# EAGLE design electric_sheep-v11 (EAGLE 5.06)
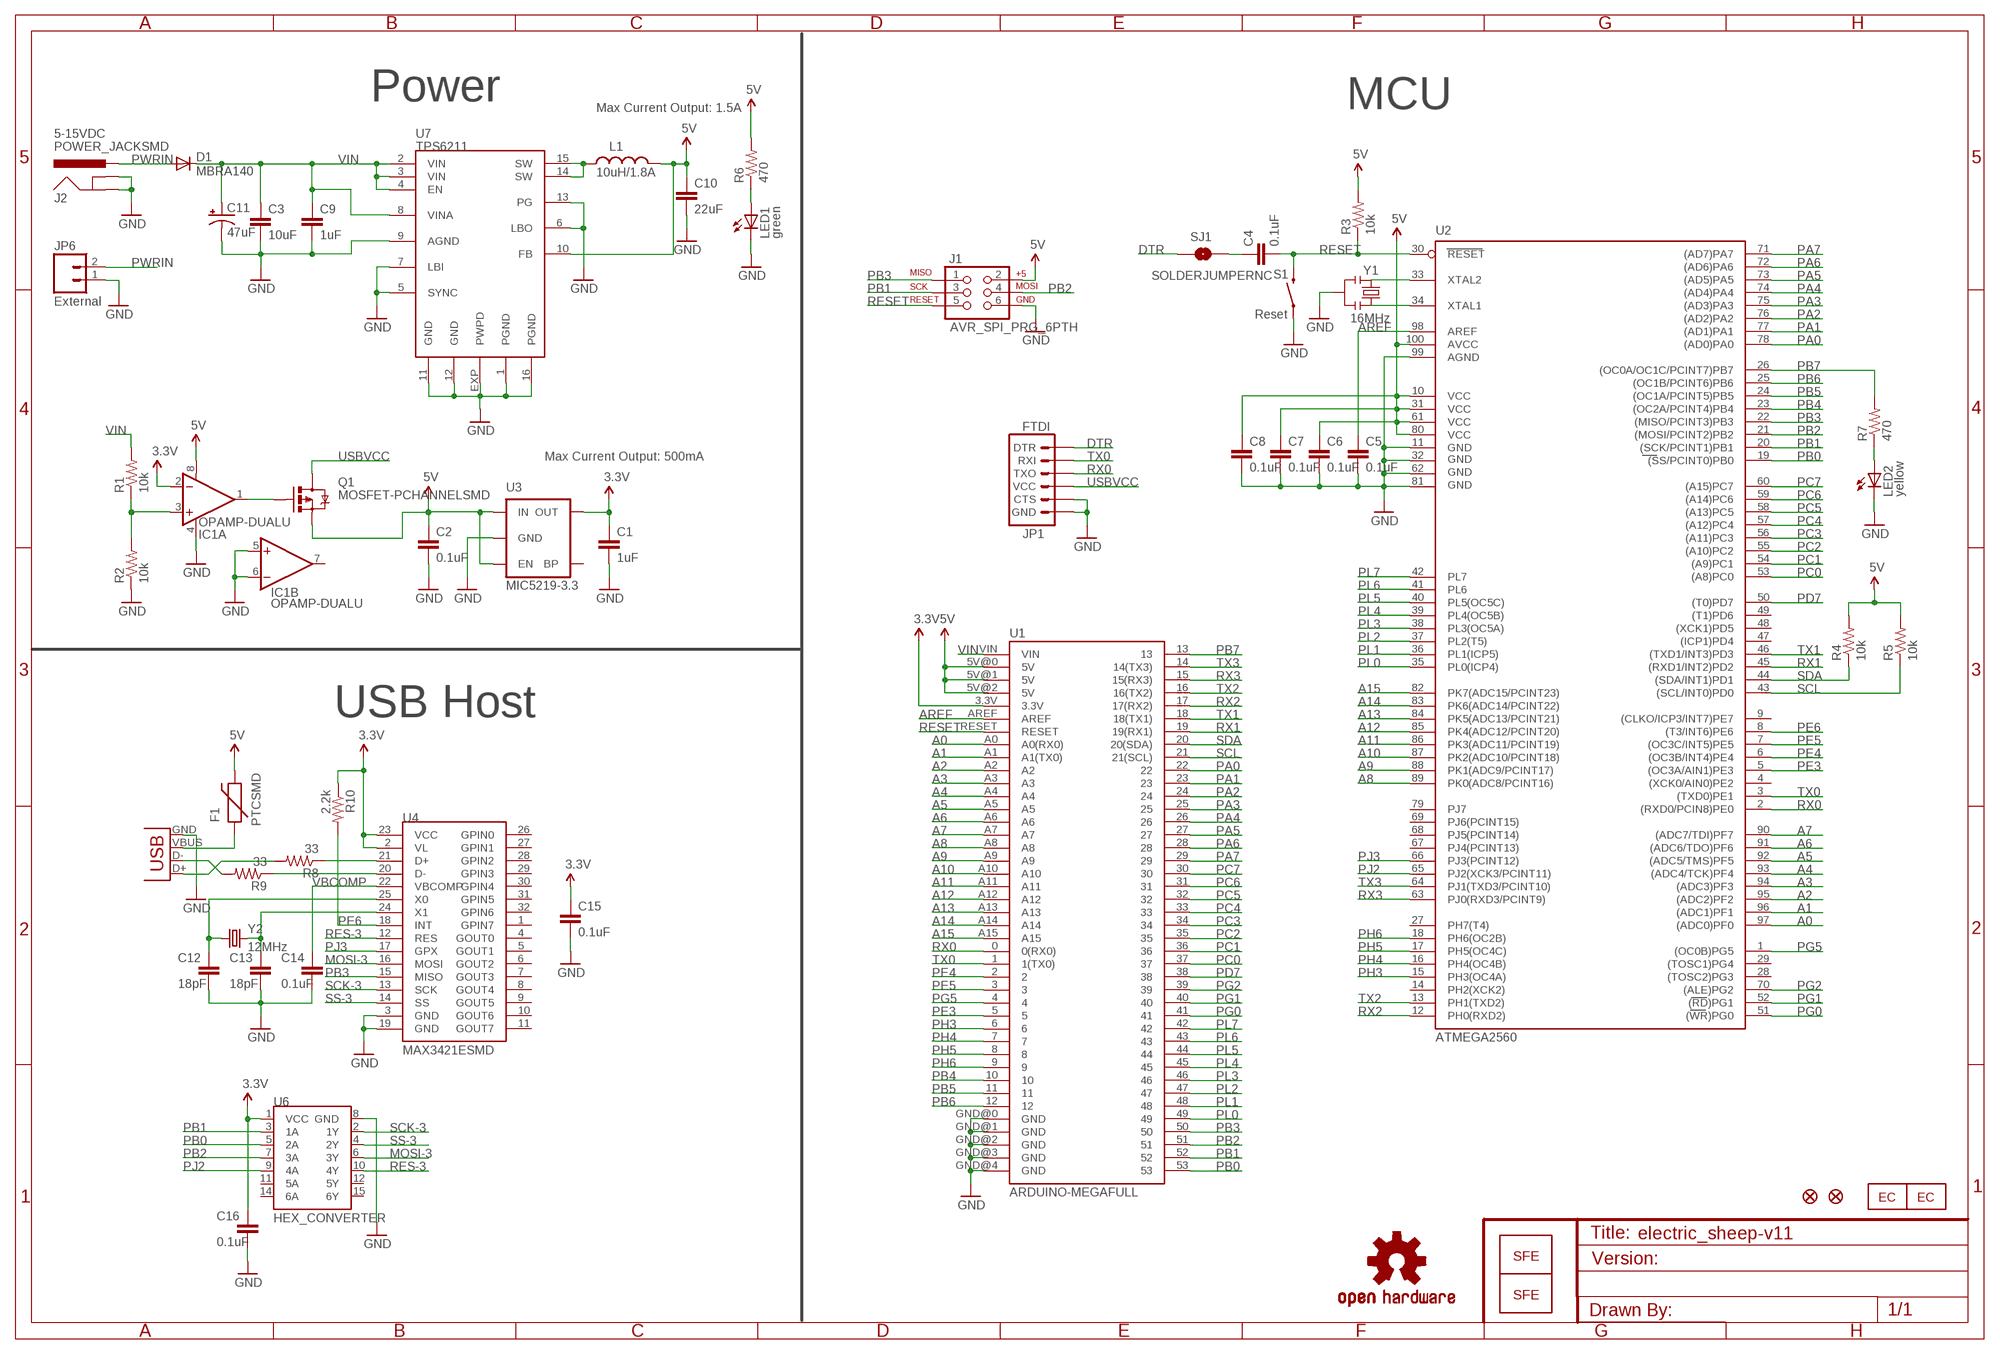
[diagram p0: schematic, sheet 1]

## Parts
C1  1uF  CAP0402-CAP  [0402-CAP]
C2  0.1uF  CAP0402-CAP  [0402-CAP]
C3  10uF  CAP1210  [1210]
C4  0.1uF  CAP0402-CAP  [0402-CAP]
C5  0.1uF  CAP0402-CAP  [0402-CAP]
C6  0.1uF  CAP0402-CAP  [0402-CAP]
C7  0.1uF  CAP0402-CAP  [0402-CAP]
C8  0.1uF  CAP0402-CAP  [0402-CAP]
C9  1uF  CAP0402-CAP  [0402-CAP]
C10  22uF  CAP1210  [1210]
C11  47uF  CAP_POLD  [PANASONIC_D]
C12  18pF  CAP0402-CAP  [0402-CAP]
C13  18pF  CAP0402-CAP  [0402-CAP]
C14  0.1uF  CAP0402-CAP  [0402-CAP]
C15  0.1uF  CAP0402-CAP  [0402-CAP]
C16  0.1uF  CAP0402-CAP  [0402-CAP]
D1  MBRA140  DIODESMA  [SMA-DIODE]
F1  PTCSMD  [PTC-1206]
IC1  OPAMP-DUALU  [SO08]
J1  AVR_SPI_PRG_6PTH  [2X3]
J2  POWER_JACKSMD  [POWER_JACK_SMD]
JP1  FTDI  ARDUINO_SERIAL_PROGRAMSMD  [1X06-SMD]
JP2  LOGO-SFENEW  [SFE-NEW-WEBLOGO]
JP3  LOGO-SFENEW  [SFE-NEW-WEBLOGO]
JP4  FIDUCIAL1X2.5  [FIDUCIAL-1X2.5]
JP5  FIDUCIAL1X2.5  [FIDUCIAL-1X2.5]
JP6  External  M02PTH  [1X02]
L1  10uH/1.8A  INDUCTORSRU5028  [SRU5028]
LED1  green  LED0603  [LED-0603]
LED2  yellow  LED0603  [LED-0603]
Q1  MOSFET-PCHANNELSMD  [SOT23-3]
R1  10k  RESISTOR0402-RES  [0402-RES]
R2  10k  RESISTOR0402-RES  [0402-RES]
R3  10k  RESISTOR0402-RES  [0402-RES]
R4  10k  RESISTOR0402-RES  [0402-RES]
R5  10k  RESISTOR0402-RES  [0402-RES]
R6  470  RESISTOR0402-RES  [0402-RES]
R7  470  RESISTOR0402-RES  [0402-RES]
R8  33  RESISTOR0402-RES  [0402-RES]
R9  33  RESISTOR0402-RES  [0402-RES]
R10  2.2k  RESISTOR0402-RES  [0402-RES]
S1  SWITCH-MOMENTARY-2SMD  [TACTILE_SWITCH_SMD]
SJ1  SOLDERJUMPERNC  [SJ_2S]
U1  ARDUINO-MEGAFULL  [ARDUINO_MEGA]
U2  ATMEGA2560AU  [TQFP100]
U3  V_REG_LDOSMD  [SOT23-5]
U4  MAX3421ESMD  [TQFP32-5MM]
U6  HEX_CONVERTER  [SO016]
U7  TPS6211  [QFN16-4X4]
U$1  OSHW-LOGOL  [OSHW-LOGO-L]
U$14  ANDROID-ELECTRIC_SHEEP_LOGO_  [ANDROID-ELECTRIC_SHEEP_LOGO]
U$15  ANDROID-ELECTRIC_SHEEP_LOGO_  [ANDROID-ELECTRIC_SHEEP_LOGO]
X1  USB-A-SMD  [USB-A-S-NOSILK-FEMALE]
Y1  RESONATORSMD  [RESONATOR-SMD]
Y2  12MHz  CRYSTAL5X3  [CRYSTAL-SMD-5X3]

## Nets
3.3V: C1.1 C15.1 C16.1 IC1.2(A:-IN) R10.1 U1.3.3V U3.5(OUT) U4.2(VL) U4.23(VCC) U6.1(VCC)
5V: C2.1 C6.1 C7.1 C8.1 C10.1 F1.2 IC1.8(A:V+) J1.2 L1.2 Q1.2(S) R3.2 R4.2 R5.2 R6.2 U1.5V@0(5V) U1.5V@1(5V) U1.5V@2(5V) U2.10(VCC) U2.31(VCC1) U2.61(VCC2) U2.80(VCC3) U2.100(AVCC) U3.1(IN) U3.3(EN) U7.10(FB)
A0: U1.A0(A0(RX0)) U2.97((ADC0)PF0)
A1: U1.A1(A1(TX0)) U2.96((ADC1)PF1)
A2: U1.A2 U2.95((ADC2)PF2)
A3: U1.A3 U2.94((ADC3)PF3)
A4: U1.A4 U2.93((ADC4/TCK)PF4)
A5: U1.A5 U2.92((ADC5/TMS)PF5)
A6: U1.A6 U2.91((ADC6/TDO)PF6)
A7: U1.A7 U2.90((ADC7/TDI)PF7)
A8: U1.A8 U2.89(PK0(ADC8/PCINT16))
A9: U1.A9 U2.88(PK1(ADC9/PCINT17))
A10: U1.A10 U2.87(PK2(ADC10/PCINT18))
A11: U1.A11 U2.86(PK3(ADC11/PCINT19))
A12: U1.A12 U2.85(PK4(ADC12/PCINT20))
A13: U1.A13 U2.84(PK5(ADC13/PCINT21))
A14: U1.A14 U2.83(PK6(ADC14/PCINT22))
A15: U1.A15 U2.82(PK7(ADC15/PCINT23))
AREF: C5.1 U1.AREF U2.98(AREF)
DTR: JP1.1(DTR) SJ1.1
GND: C1.2 C2.2 C3.2 C5.2 C6.2 C7.2 C8.2 C9.2 C10.2 C11.- C12.2 C13.2 C14.2 C15.2 C16.2 IC1.4(A:V-) IC1.5(B:+IN) IC1.6(B:-IN) J1.6 J2.GND(GNDBREAK) J2.P$4(GND) JP1.5(CTS) JP1.6(GND) JP6.1 LED1.C LED2.C R2.1 S1.1 U1.GND@0(GND) U1.GND@1(GND) U1.GND@2(GND) U1.GND@3(GND) U1.GND@4(GND) U2.11(GND) U2.32(GND1) U2.62(GND2) U2.81(GND3) U2.99(AGND) U3.2(GND) U4.3(GND) U4.19(GND) U6.8(GND) U7.1(PGND) U7.5(SYNC) U7.6(LBO) U7.7(LBI) U7.9(AGND) U7.11(GND) U7.12(GND) U7.13(PG) U7.16(PGND) U7.EXP(PWPD) X1.GND Y1.2
MOSI-3: U4.16(MOSI) U6.6(3Y)
N$1: IC1.3(A:+IN) R1.1 R2.2
N$2: LED1.A R6.1
N$3: LED2.A R7.1
N$4: C4.1 SJ1.2
N$5: IC1.1(A:OUT) Q1.1(G)
N$11: L1.1 U7.14(SW) U7.15(SW)
N$13: R8.1 U4.21(D+)
N$14: R9.1 U4.20(D-)
N$15: R9.2 X1.D-
N$16: R8.2 X1.D+
N$18: F1.1 X1.VBUS
N$19: C12.1 U4.25(X0) Y2.1
N$20: C13.1 U4.24(X1) Y2.3
N$73: U2.33(XTAL2) Y1.1
N$74: U2.34(XTAL1) Y1.3
PA0: U1.22 U2.78((AD0)PA0)
PA1: U1.23 U2.77((AD1)PA1)
PA2: U1.24 U2.76((AD2)PA2)
PA3: U1.25 U2.75((AD3)PA3)
PA4: U1.26 U2.74((AD4)PA4)
PA5: U1.27 U2.73((AD5)PA5)
PA6: U1.28 U2.72((AD6)PA6)
PA7: U1.29 U2.71((AD7)PA7)
PB0: U1.53 U2.19((SS/PCINT0)PB0) U6.5(2A)
PB1: J1.3 U1.52 U2.20((SCK/PCINT1)PB1) U6.3(1A)
PB2: J1.4 U1.51 U2.21((MOSI/PCINT2)PB2) U6.7(3A)
PB3: J1.1 U1.50 U2.22((MISO/PCINT3)PB3) U4.15(MISO)
PB4: U1.10 U2.23((OC2A/PCINT4)PB4)
PB5: U1.11 U2.24((OC1A/PCINT5)PB5)
PB6: U1.12 U2.25((OC1B/PCINT6)PB6)
PB7: R7.2 U1.13 U2.26((OC0A/OC1C/PCINT7)PB7)
PC0: U1.37 U2.53((A8)PC0)
PC1: U1.36 U2.54((A9)PC1)
PC2: U1.35 U2.55((A10)PC2)
PC3: U1.34 U2.56((A11)PC3)
PC4: U1.33 U2.57((A12)PC4)
PC5: U1.32 U2.58((A13)PC5)
PC6: U1.31 U2.59((A14)PC6)
PC7: U1.30 U2.60((A15)PC7)
PD7: U1.38 U2.50((T0)PD7)
PE3: U1.5 U2.5((OC3A/AIN1)PE3)
PE4: U1.2 U2.6((OC3B/INT4)PE4)
PE5: U1.3 U2.7((OC3C/INT5)PE5)
PE6: R10.2 U2.8((T3/INT6)PE6) U4.18(INT)
PG0: U1.41 U2.51((WR)PG0)
PG1: U1.40 U2.52((RD)PG1)
PG2: U1.39 U2.70((ALE)PG2)
PG5: U1.4 U2.1((OC0B)PG5)
PH3: U1.6 U2.15(PH3(OC4A))
PH4: U1.7 U2.16(PH4(OC4B))
PH5: U1.8 U2.17(PH5(OC4C))
PH6: U1.9 U2.18(PH6(OC2B))
PJ2: U2.65(PJ2(XCK3/PCINT11)) U6.9(4A)
PJ3: U2.66(PJ3(PCINT12)) U4.17(GPX)
PL0: U1.49 U2.35(PL0(ICP4))
PL1: U1.48 U2.36(PL1(ICP5))
PL2: U1.47 U2.37(PL2(T5))
PL3: U1.46 U2.38(PL3(OC5A))
PL4: U1.45 U2.39(PL4(OC5B))
PL5: U1.44 U2.40(PL5(OC5C))
PL6: U1.43 U2.41(PL6)
PL7: U1.42 U2.42(PL7)
PWRIN: D1.A J2.VIN0(PWR) JP6.2
RES-3: U4.12(RES) U6.10(4Y)
RESET: C4.2 J1.5 R3.1 S1.3 U1.RESET U2.30(RESET)
RX0: JP1.3(TXO) U1.0(0(RX0)) U2.2((RXD0/PCIN8)PE0)
RX1: U1.19(19(RX1)) U2.45((RXD1/INT2)PD2)
RX2: U1.17(17(RX2)) U2.12(PH0(RXD2))
RX3: U1.15(15(RX3)) U2.63(PJ0(RXD3/PCINT9))
SCK-3: U4.13(SCK) U6.2(1Y)
SCL: R5.1 U1.21(21(SCL)) U2.43((SCL/INT0)PD0)
SDA: R4.1 U1.20(20(SDA)) U2.44((SDA/INT1)PD1)
SS-3: U4.14(SS) U6.4(2Y)
TX0: JP1.2(RXI) U1.1(1(TX0)) U2.3((TXD0)PE1)
TX1: U1.18(18(TX1)) U2.46((TXD1/INT3)PD3)
TX2: U1.16(16(TX2)) U2.13(PH1(TXD2))
TX3: U1.14(14(TX3)) U2.64(PJ1(TXD3/PCINT10))
USBVCC: JP1.4(VCC) Q1.3(D)
VBCOMP: C14.1 U4.22(VBCOMP)
VIN: C3.1 C9.1 C11.+ D1.C R1.2 U1.VIN U7.2(VIN) U7.3(VIN) U7.4(EN) U7.8(VINA)
Unconnected: IC1.7(B:OUT) U2.4((XCK0/AIN0)PE2) U2.9((CLKO/ICP3/INT7)PE7) U2.14(PH2(XCK2)) U2.27(PH7(T4)) U2.28((TOSC2)PG3) U2.29((TOSC1)PG4) U2.47((ICP1)PD4) U2.48((XCK1)PD5) U2.49((T1)PD6) U2.67(PJ4(PCINT13)) U2.68(PJ5(PCINT14)) U2.69(PJ6(PCINT15)) U2.79(PJ7) U3.4(BP) U4.1(GPIN7) U4.4(GOUT0) U4.5(GOUT1) U4.6(GOUT2) U4.7(GOUT3) U4.8(GOUT4) U4.9(GOUT5) U4.10(GOUT6) U4.11(GOUT7) U4.26(GPIN0) U4.27(GPIN1) U4.28(GPIN2) U4.29(GPIN3) U4.30(GPIN4) U4.31(GPIN5) U4.32(GPIN6) U6.11(5A) U6.12(5Y) U6.14(6A) U6.15(6Y)

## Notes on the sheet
- Power | MCU
- Max Current Output: 1.5A
- 5-15VDC
- Reset
- 16MHz
- Max Current Output: 500mA
- MIC5219-3.3
- USB Host
- ATMEGA2560

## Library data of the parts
C1-C10 C12-C16 = SparkFun:CAP: Capacitor
C11 = SparkFun:CAP_POL: Capacitor Polarized
D1 = SparkFun:DIODE: Diode
F1 = SparkFun:PTC: Resettable Fuse PTC
IC1 = SparkFun:OPAMP-DUAL: Operational Amplifier
J1 = SparkFun:AVR_SPI_PRG_6: AVR ISP 6 Pin This is the reduced ISP connector for AVR programming. Common on Arduino. This footprint will take up less PCB space and can be used with a 10-pin to 6-pin adapter such as SKU: BOB-08508
J2 = SparkFun:POWER_JACK: Power Jack This is the standard 5.5mm barrel jack for power. The PTH is the most common, proven, reliable, footprint. All others are experimental. The Slot footprint only works if the mill layer is transmitted to the PCB fab house so be warned. Spark Fun Electronics SKU : PRT-00119. Mating wall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
JP1 = SparkFun:ARDUINO_SERIAL_PROGRAM
JP2 JP3 = SparkFun:LOGO-SFE: Spark Fun Electronics PCB Logo
JP4 JP5 = abes:FIDUCIAL: Fiducial Alignment Points
JP6 = SparkFun:M02: Header 2
L1 = SparkFun:INDUCTOR: Inductors
LED1 LED2 = SparkFun:LED: LEDs
Q1 = SparkFun:MOSFET-PCHANNEL
R1-R10 = SparkFun:RESISTOR: Resistor
S1 = SparkFun:SWITCH-MOMENTARY-2
SJ1 = SparkFun:SOLDERJUMPER: Solder Jumper
U1 = SparkFun:ARDUINO-MEGA: Arduino Mega footprint connections
U2 = SparkFun:ATMEGA2560: MICROCONTROLLER 64/128/256 Kbytes FLASH 4 Kbytes EEPROM 8 Kbytes SRAM 86 General Purpose I/O pins 12-channels16-bit PWM 4 x Serial USARTs 16-channels 10-bit A/D
U3 = SparkFun:V_REG_LDO: Voltage Regulator LDO Standard 150mA LDO voltage regulator in SOT-23 layout. Micrel part MIC5205. BP (by-pass) pin is used to lower output noise with 470pF cap.
U4 = SparkFun:MAX3421E: USB Peripheral/Host Controller w/ SPI
U6 = SparkFun:HEX_CONVERTER
U7 = SparkFun:TPS6211*: TPS62112: 1.5A Step-Down Converter
U$1 = SparkFun:OSHW-LOGO: Open Source Hardware Logo This logo indicates the piece of hardware it is found on incorporates a OSHW license and/or adheres to the definition of open source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
U$14 U$15 = SparkFun:ANDROID-ELECTRIC_SHEEP_LOGO
X1 = SparkFun:USB: USB Connectors USB-B-PTH is fully proven SKU : PRT-00139 USB-miniB is fully proven SKU : PRT-00587 USB-A-PCB is untested. USB-A-H is throughly reviewed, but untested. Spark Fun Electronics SKU : PRT-00437 USB-B-SMT is throughly reviewed, but untested. Needs silkscreen touching up. USB-A-S has not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
Y1 = SparkFun:RESONATOR: Resonator Small SMD resonator. This is the itty bitty 10/20MHz resonators with built in caps. CSTCE10M0G55 and CSTCE20M0V53. Footprint has been reviewed closely but hasn't been tested yet.
Y2 = SparkFun:CRYSTAL: Crystals

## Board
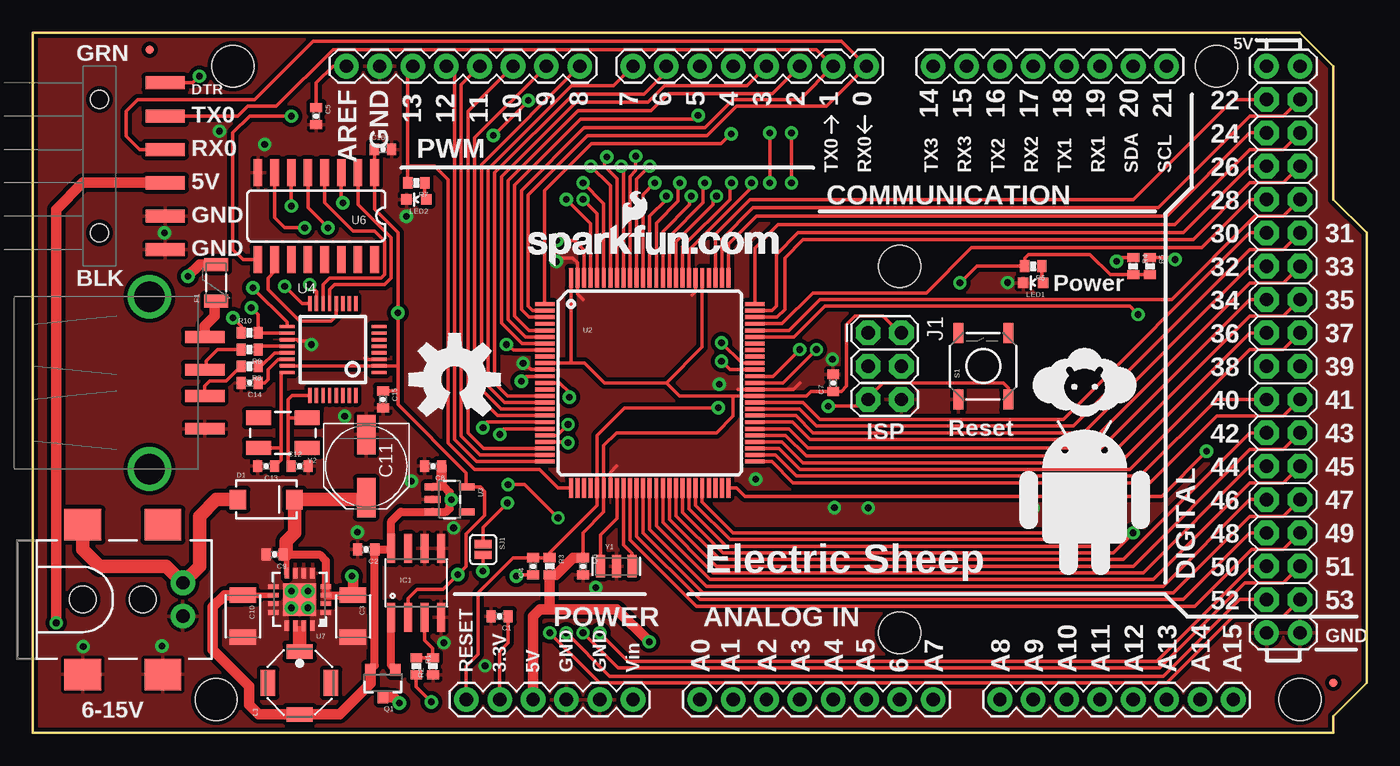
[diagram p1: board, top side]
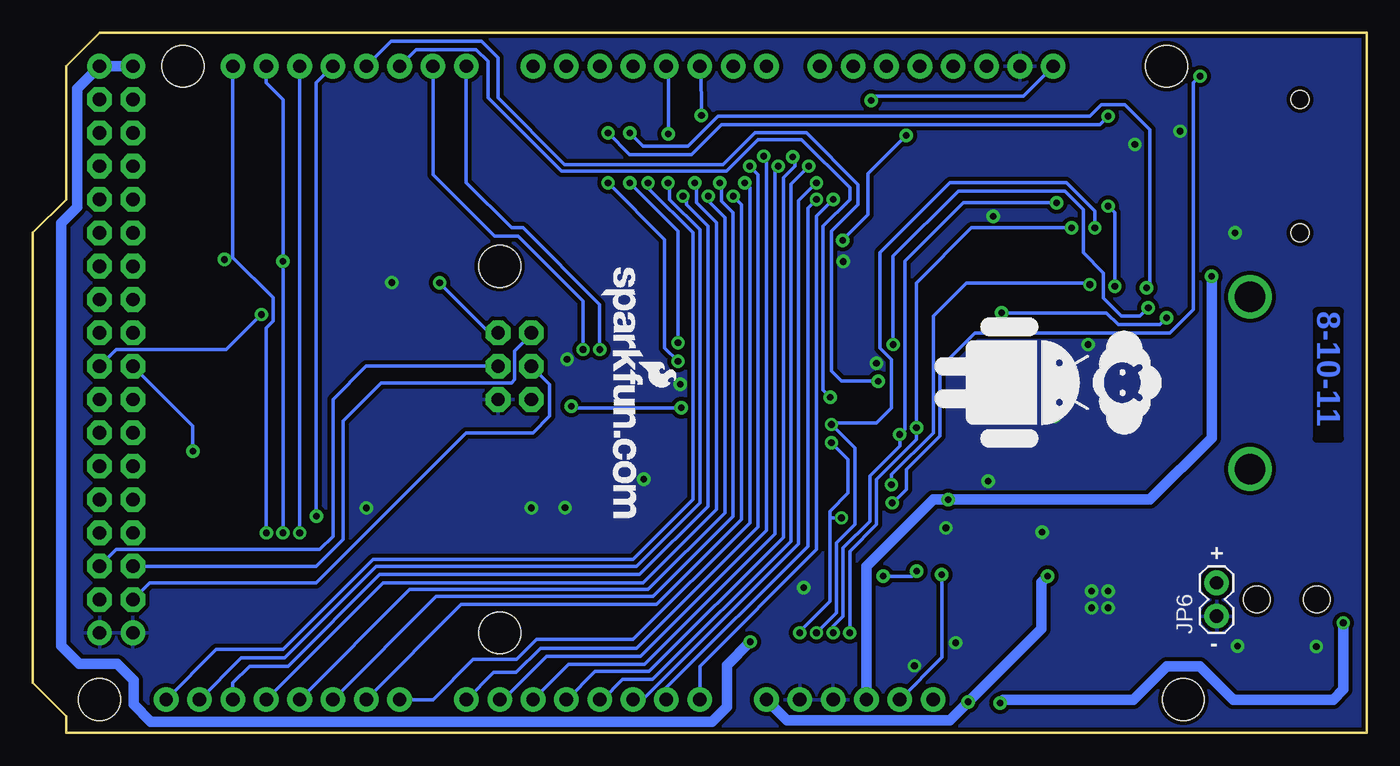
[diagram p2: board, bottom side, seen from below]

Size 101.6 x 53.34 mm. Coordinates in mm from the lower left corner, seen from the top.
Copper layers (1*16): Top 0.035mm / dielectric 1.5mm / Bottom 0.035mm
Design rules "SparkFun": minimum track width 8mil, minimum drill 20mil, track to track 8mil, track to pad 8mil, pad to pad 8mil, via to via 8mil, smd to smd 8mil, copper to edge 8mil, drill to drill 8mil, minimum pad ring 12mil, minimum via ring 10mil, stop-mask expansion 4mil, vias tented up to drill 20mil, thermal gap 10mil

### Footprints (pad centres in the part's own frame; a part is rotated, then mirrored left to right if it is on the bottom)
0402-CAP = smd 0.7 x 0.9: 1 -0.65,0; 2 0.65,0
1210 = smd 1.2 x 2: 1 -1.6,0; 2 1.6,0
PANASONIC_D = smd 3 x 1.4: + 2.4,0; - -2.4,0
SMA-DIODE = smd 1.27 x 1.47: A -2.15,0; C 2.15,0
PTC-1206 = smd 1 x 1.8: 1 -1.4,0; 2 1.4,0
SO08 = smd 0.61 x 2.21: 1 -1.905,-2.616; 2 -0.635,-2.616; 3 0.635,-2.616; 4 1.905,-2.616; 5 1.905,2.616; 6 0.635,2.616; 7 -0.635,2.616; 8 -1.905,2.616
2X3 = drill 1.016 pad 1.88 octagon: 1 0,0; 2 0,2.54; 3 2.54,0; 4 2.54,2.54; 5 5.08,0; 6 5.08,2.54
POWER_JACK_SMD = smd 2.8 x 2.4: GND 0,-5.7; P$4 6.1,-5.7; VIN0 0,5.7; VIN1 6.1,5.7 | hole 2.032: 0,0; 4.572,0
1X06-SMD = smd 1 x 3: 1 -6.35,5; 2 -3.81,5; 3 -1.27,5; 4 1.27,5; 5 3.81,5; 6 6.35,5 | hole 1.4: -5.08,0; 5.08,0
FIDUCIAL-1X2.5 = smd 0.635 x 0.635: 1 0,0
1X02 = drill 1.016 pad 1.88 round: 1 0,0; 2 2.54,0
SRU5028 = smd 1.1 x 2: 1 2.4,0; 2 -2.4,0 | smd 2 x 1.1: P$1 0,2.4; P$2 0,-2.4
LED-0603 = smd 0.8 x 0.8: A 0,-0.75; C 0,0.75
SOT23-3 = smd 0.8 x 0.9: 1 -0.95,-1; 2 0.95,-1; 3 0,1.1
0402-RES = smd 0.7 x 0.9: 1 -0.65,0; 2 0.65,0
TACTILE_SWITCH_SMD = smd 1.524 x 0.762: 1 -2.54,1.905; 2 2.54,1.905; 3 -2.54,-1.905; 4 2.54,-1.905
SJ_2S = smd 0.635 x 1.27: 1 -0.412,0; 2 0.412,0
ARDUINO_MEGA = drill 1.016 pad 1.88 round: 0 63.5,50.8; 1 60.96,50.8; 2 58.42,50.8; 3 55.88,50.8; 3.3V 35.56,2.54; 4 53.34,50.8; 5 50.8,50.8; 5V@0 38.1,2.54; 5V@1 93.98,50.8; 5V@2 96.52,50.8; 6 48.26,50.8; 7 45.72,50.8; 8 41.656,50.8; 9 39.116,50.8; 10 36.576,50.8; 11 34.036,50.8; 12 31.496,50.8; 13 28.956,50.8; 14 68.58,50.8; 15 71.12,50.8; 16 73.66,50.8; 17 76.2,50.8; 18 78.74,50.8; 19 81.28,50.8; 20 83.82,50.8; 21 86.36,50.8; A0 50.8,2.54; A1 53.34,2.54; A2 55.88,2.54; A3 58.42,2.54; A4 60.96,2.54; A5 63.5,2.54; A6 66.04,2.54; A7 68.58,2.54; A8 73.66,2.54; A9 76.2,2.54; A10 78.74,2.54; A11 81.28,2.54; A12 83.82,2.54; A13 86.36,2.54; A14 88.9,2.54; A15 91.44,2.54; AREF 23.876,50.8; GND@0 40.64,2.54; GND@1 43.18,2.54; GND@2 93.98,7.62; GND@3 96.52,7.62; GND@4 26.416,50.8; RESET 33.02,2.54; VIN 45.72,2.54 | drill 1.016 pad 1.88 octagon: 22 93.98,48.26; 23 96.52,48.26; 24 93.98,45.72; 25 96.52,45.72; 26 93.98,43.18; 27 96.52,43.18; 28 93.98,40.64; 29 96.52,40.64; 30 93.98,38.1; 31 96.52,38.1; 32 93.98,35.56; 33 96.52,35.56; 34 93.98,33.02; 35 96.52,33.02; 36 93.98,30.48; 37 96.52,30.48; 38 93.98,27.94; 39 96.52,27.94; 40 93.98,25.4; 41 96.52,25.4; 42 93.98,22.86; 43 96.52,22.86; 44 93.98,20.32; 45 96.52,20.32; 46 93.98,17.78; 47 96.52,17.78; 48 93.98,15.24; 49 96.52,15.24; 50 93.98,12.7; 51 96.52,12.7; 52 93.98,10.16; 53 96.52,10.16 | hole 3.2: 15.24,50.8; 13.97,2.54; 66.04,35.56; 66.04,7.62; 90.17,50.8; 96.52,2.54
TQFP100 = smd 1.5 x 0.3: 1 -8,6; 2 -8,5.5; 3 -8,5; 4 -8,4.5; 5 -8,4; 6 -8,3.5; 7 -8,3; 8 -8,2.5; 9 -8,2; 10 -8,1.5; 11 -8,1; 12 -8,0.5; 13 -8,0; 14 -8,-0.5; 15 -8,-1; 16 -8,-1.5; 17 -8,-2; 18 -8,-2.5; 19 -8,-3; 20 -8,-3.5; 21 -8,-4; 22 -8,-4.5; 23 -8,-5; 24 -8,-5.5; 25 -8,-6; 51 8,-6; 52 8,-5.5; 53 8,-5; 54 8,-4.5; 55 8,-4; 56 8,-3.5; 57 8,-3; 58 8,-2.5; 59 8,-2; 60 8,-1.5; 61 8,-1; 62 8,-0.5; 63 8,0; 64 8,0.5; 65 8,1; 66 8,1.5; 67 8,2; 68 8,2.5; 69 8,3; 70 8,3.5; 71 8,4; 72 8,4.5; 73 8,5; 74 8,5.5; 75 8,6 | smd 0.3 x 1.5: 26 -6,-8; 27 -5.5,-8; 28 -5,-8; 29 -4.5,-8; 30 -4,-8; 31 -3.5,-8; 32 -3,-8; 33 -2.5,-8; 34 -2,-8; 35 -1.5,-8; 36 -1,-8; 37 -0.5,-8; 38 0,-8; 39 0.5,-8; 40 1,-8; 41 1.5,-8; 42 2,-8; 43 2.5,-8; 44 3,-8; 45 3.5,-8; 46 4,-8; 47 4.5,-8; 48 5,-8; 49 5.5,-8; 50 6,-8; 76 6,8; 77 5.5,8; 78 5,8; 79 4.5,8; 80 4,8; 81 3.5,8; 82 3,8; 83 2.5,8; 84 2,8; 85 1.5,8; 86 1,8; 87 0.5,8; 88 0,8; 89 -0.5,8; 90 -1,8; 91 -1.5,8; 92 -2,8; 93 -2.5,8; 94 -3,8; 95 -3.5,8; 96 -4,8; 97 -4.5,8; 98 -5,8; 99 -5.5,8; 100 -6,8
SOT23-5 = smd 0.55 x 1.2: 1 -0.95,-1.3; 2 0,-1.3; 3 0.95,-1.3; 4 0.95,1.3; 5 -0.95,1.3
TQFP32-5MM = smd 1.143 x 0.254: 1 -3.5,1.75; 2 -3.5,1.25; 3 -3.5,0.75; 4 -3.5,0.25; 5 -3.5,-0.25; 6 -3.5,-0.75; 7 -3.5,-1.25; 8 -3.5,-1.75; 17 3.5,-1.75; 18 3.5,-1.25; 19 3.5,-0.75; 20 3.5,-0.25; 21 3.5,0.25; 22 3.5,0.75; 23 3.5,1.25; 24 3.5,1.75 | smd 0.254 x 1.143: 9 -1.75,-3.5; 10 -1.25,-3.5; 11 -0.75,-3.5; 12 -0.25,-3.5; 13 0.25,-3.5; 14 0.75,-3.5; 15 1.25,-3.5; 16 1.75,-3.5; 25 1.75,3.5; 26 1.25,3.5; 27 0.75,3.5; 28 0.25,3.5; 29 -0.25,3.5; 30 -0.75,3.5; 31 -1.25,3.5; 32 -1.75,3.5
SO016 = smd 0.66 x 2.032: 1 -4.445,-3.315; 2 -3.175,-3.315; 3 -1.905,-3.315; 4 -0.635,-3.315; 5 0.635,-3.315; 6 1.905,-3.315; 7 3.175,-3.315; 8 4.445,-3.315; 9 4.445,3.315; 10 3.175,3.315; 11 1.905,3.315; 12 0.635,3.315; 13 -0.635,3.315; 14 -1.905,3.315; 15 -3.175,3.315; 16 -4.445,3.315
QFN16-4X4 = smd 0.8 x 0.35: 1 -2,0.975; 2 -2,0.325; 3 -2,-0.325; 4 -2,-0.975; 9 2,-0.975; 10 2,-0.325; 11 2,0.325; 12 2,0.975 | smd 0.35 x 0.8: 5 -0.975,-2; 6 -0.325,-2; 7 0.325,-2; 8 0.975,-2; 13 0.975,2; 14 0.325,2; 15 -0.325,2; 16 -0.975,2 | smd 2.5 x 2.5: EXP 0,0
USB-A-S-NOSILK-FEMALE = smd 3 x 0.9: D+ 4.212,-1; D- 4.212,1; GND 4.212,-3.5; VBUS 4.212,3.5 | drill 2.311 round: P$5 0,-6.566; P$6 0,6.566
RESONATOR-SMD = smd 0.7 x 1.7: 1 -1.2,0; 2 0,0; 3 1.2,0
CRYSTAL-SMD-5X3 = smd 1.9 x 1.1: 1 -1.85,-1.15; 2 1.85,-1.15; 3 1.85,1.15; 4 -1.85,1.15

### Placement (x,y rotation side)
C1  35.56,8.89 180 top
C2  25.4,13.97 180 top
C3  24.38,8.89 270 top
C4  38.1,12.7 90 top
C5  21.59,46.99 270 top
C6  41.91,12.7 270 top
C7  60.96,26.67 90 top
C8  30.48,20.32 180 top
C9  18.41,13.59 180 top
C10  16,8.89 270 top
C11  25.4,20.32 270 top
C12  20.32,20.32 0 top
C13  17.78,20.32 180 top
C14  16.51,26.67 180 top
C15  26.67,25.4 270 top
C16  26.67,44.45 0 top
D1  17.78,17.78 0 top
F1  13.97,34.29 90 top
IC1  29.21,11.43 0 top
J1  63.63,30.48 270 top
J2  3.81,10.16 0 top
JP1  5.08,43.18 270 top
JP2  37.72,35.56 0 top
JP3  58.29,35.43 270 bottom
JP4  8.89,52.07 0 top
JP5  99.06,3.81 0 top
JP6  11.43,8.89 90 bottom
L1  20.32,3.81 90 top
LED1  76.2,34.29 90 top
LED2  29.21,40.64 90 top
Q1  26.67,3.81 180 top
R1  29.21,5.08 270 top
R2  30.48,5.08 90 top
R3  39.37,12.7 270 top
R4  83.82,35.56 270 top
R5  85.09,35.56 270 top
R6  76.2,35.56 180 top
R7  29.21,41.91 180 top
R8  16.51,27.94 180 top
R9  16.51,29.21 180 top
R10  16.51,30.48 0 top
S1  72.39,27.94 90 top
SJ1  34.29,13.97 270 top
U1  0,0 0 top
U2  46.99,26.67 0 top
U3  31.75,17.78 270 top
U4  22.86,29.21 180 top
U6  21.59,39.37 180 top
U7  20.32,10.16 180 top
U$1  32.13,26.92 0 top
U$14  33.02,31.75 270 bottom
U$15  75.06,11.94 0 top
X1  8.89,26.67 0 top
Y1  44.45,12.7 0 top
Y2  19.05,22.86 180 top

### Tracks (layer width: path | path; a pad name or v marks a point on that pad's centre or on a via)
3.3V  (via drill 0.51)
  Top 0.254: 26.02,42.7 C16.1 | 26.02,42.7 U6.1 | 26.02,42.7 26.02,39.89 27.81,38.1 v27.81,32 27.81,27.94 | C15.1 26.68,26.04 27.81,26.04 | C1.1 36.21,6.87 35.56,6.22 U1.3.3V | 27.81,26.04 27.81,27.94 | 27.81,26.04 27.81,25.02 33.02,19.81 33.02,18.76 U3.5 34.1,18.73 34.42,18.41 34.42,16.59 32.99,15.16 32.99,12.68 v32.38,12.06 31.24,10.92 29.26,10.92 28.57,10.24 IC1.2 | R10.1 15.86,31 v15.24,31.62 | 27.81,27.94 27.79,27.96 U4.2 U4.23
  Bottom 0.254: v27.81,32 19.81,32 18.92,31.11 15.75,31.11 v15.24,31.62 | U1.3.3V 32.36,5.74 32.36,12.04 v32.38,12.06
5V  (via drill 0.51)
  Top 0.203: 31.36,18.73 31.13,18.96
  Top 0.254: R5.2 R4.2 82.06,34.91 80.52,36.45 75.82,36.45 75.56,36.2 75.56,35.58 | 75.56,35.58 71.9,35.58 v70.61,34.29 | 40.97,28.17 42.04,28.17 43.54,26.67 48.26,26.67 | 48.26,26.67 49.26,25.67 53.34,25.67 | 48.26,26.67 50.99,29.4 U2.80 | C6.1 41.91,15.24 43.49,16.82 U2.31 43.49,21.9 44.45,22.86 52.07,22.86 53.34,24.13 53.34,25.67 | U2.100 40.99,28.19 40.97,28.17 | 40.97,28.17 U2.10 | 53.34,25.67 U2.61 58.91,25.67 59.26,26.02 C7.1 61.58,26.02 61.98,26.42 61.98,31.11 62.61,31.75 64.77,31.75 66.04,30.48 J1.2 | 31.75,18.34 31.75,17.91 v31.88,17.78 | 75.56,35.58 R6.2
  Top 0.406: U7.10 C10.1
  Top 0.61: U3.1 31.36,18.73 31.75,18.34 31.75,17.09 31.5,16.84 U3.3 | U3.3 | U3.3 28.02,16.84 27.3,16.13 IC1.8 27.23,13.97 C2.1 26.05,5.14 Q1.2
  Top 0.813: C6.1 41.16,13.35 39.86,12.05 R3.2 39.37,9.42 | F1.2 12.7,35.69 v11.81,34.8 | C10.1 14.6,10.48 13.72,9.6 13.72,6.33 16.48,3.56 16.48,2.13 17.21,1.41 L1.2 23.36,1.41 25.72,3.77 Q1.2 | 31.13,18.96 C8.1 | v46.97,6.93 44.48,9.42 39.37,9.42 | 39.37,9.42 38.63,9.42 38.1,8.89 U1.5V@0
  Bottom 0.254: v70.61,34.29 66.8,30.48 J1.2
  Bottom 0.813: U1.5V@1 U1.5V@2 98.22,49.1 98.22,40.06 99.44,38.84 99.44,6.63 98.07,5.26 95.17,5.26 93.93,4.01 93.93,2.18 92.61,0.86 49.89,0.86 48.74,2.01 48.74,5.16 v46.97,6.93 | v11.81,34.8 11.81,22.48 16.51,17.78 v31.88,17.78 33.02,17.78 38.1,12.7 U1.5V@0
A0  (via drill 0.51)
  Top 0.254: U2.97 42.49,38.79 v40.64,40.64
  Bottom 0.254: U1.A0 50.8,5.08 41.91,13.97 41.91,39.37 v40.64,40.64
A1  (via drill 0.51)
  Top 0.254: U2.96 42.99,39.56 v41.91,40.64
  Bottom 0.254: U1.A1 53.34,3.45 42.57,14.22 42.57,39.98 v41.91,40.64
A2  (via drill 0.51)
  Top 0.254: U2.95 43.49,40.33 v41.91,41.91
  Bottom 0.254: U1.A2 55.14,2.54 43.28,14.4 43.28,40.54 v41.91,41.91
A3  (via drill 0.51)
  Top 0.254: U2.94 43.99,41.68 v42.49,43.18
  Bottom 0.254: U1.A3 58.19,2.54 56.67,4.06 54.41,4.06 43.87,14.61 43.87,41.81 v42.49,43.18
A4  (via drill 0.51)
  Top 0.254: U2.93 44.49,42.23 43.54,43.18 43.54,43.71 v43.71,43.89
  Bottom 0.254: U1.A4 60.91,2.54 58.78,4.67 54.66,4.67 44.42,14.91 44.42,42.29 43.54,43.18 43.54,43.71 v43.71,43.89
A5  (via drill 0.51)
  Top 0.254: U2.92 44.99,43.02 v44.83,43.18
  Bottom 0.254: U1.A5 60.81,5.23 55.02,5.23 45.09,15.16 45.09,42.93 v44.83,43.18
A6  (via drill 0.51)
  Top 0.254: U2.91 45.49,42.39 45.92,42.82 v45.92,43.94
  Bottom 0.254: U1.A6 65.79,2.54 62.48,5.84 55.32,5.84 45.72,15.44 45.72,43.74 v45.92,43.94
A7  (via drill 0.51)
  Top 0.254: U2.90 45.99,42.18 v46.99,43.18
  Bottom 0.254: U1.A7 68.56,2.54 66.5,4.6 64.8,4.6 62.94,6.45 55.6,6.45 46.35,15.7 46.35,42.55 v46.99,43.18
A8  (via drill 0.51)
  Top 0.254: U2.89 46.49,41.03 v47.37,41.91
  Bottom 0.254: U1.A8 71.12,2.54 68.07,5.59 64.77,5.59 63.25,7.11 55.88,7.11 46.99,16 46.99,41.53 v47.37,41.91
A9  (via drill 0.51)
  Top 0.254: U2.88 46.99,39.37 48.26,40.64 v48.26,40.89
  Bottom 0.254: U1.A9 68.96,9.78 54.1,9.78 47.62,16.26 47.62,40.26 v48.26,40.89
A10  (via drill 0.51)
  Top 0.254: U2.87 47.49,38.85 49.15,40.51 49.15,41.78 v49.28,41.91
  Bottom 0.254: U1.A10 70.87,10.41 54.36,10.41 48.26,16.51 48.26,39.62 49.15,40.51 49.15,41.78 v49.28,41.91
A11  (via drill 0.51)
  Top 0.254: U2.86 47.99,38.21 50.04,40.26 50.04,40.77 v50.16,40.89
  Bottom 0.254: U1.A11 72.9,10.92 54.74,10.92 48.9,16.76 48.9,39.24 50.04,40.39 50.04,40.77 v50.16,40.89
A12  (via drill 0.51)
  Top 0.254: U2.85 48.49,37.82 51.05,40.39 51.05,41.78 v51.18,41.91
  Bottom 0.254: U1.A12 74.93,11.43 55.12,11.43 49.53,17.02 49.53,38.86 51.05,40.39 51.05,41.78 v51.18,41.91
A13  (via drill 0.51)
  Top 0.254: U2.84 48.99,37.43 51.82,40.26 51.82,40.64 v52.07,40.89
  Bottom 0.254: U1.A13 86.36,3.81 85.09,5.08 82.17,5.08 75.18,12.06 55.37,12.06 50.16,17.27 50.16,38.61 51.82,40.26 51.82,40.64 v52.07,40.89
A14  (via drill 0.51)
  Top 0.254: U2.83 49.49,37.04 53.09,40.64 53.09,41.78 v53.21,41.91
  Bottom 0.254: U1.A14 85.72,5.71 82.42,5.71 75.44,12.7 55.63,12.7 50.8,17.53 50.8,38.35 53.09,40.64 53.09,41.78 v53.21,41.91
A15  (via drill 0.51)
  Top 0.254: U2.82 49.99,36.78 54.74,41.53 v54.74,41.91
  Bottom 0.254: U1.A15 87.63,6.35 82.55,6.35 75.69,13.21 55.88,13.21 51.31,17.78 51.31,38.1 54.61,41.4 54.61,41.78 v54.74,41.91
AREF  (via drill 0.51)
  Top 0.254: 40.18,37.52 v39.9,37.52 41.27,37.52 41.99,36.8 U2.98 | C5.1 21.59,49.53 22.86,50.8 U1.AREF | v37.74,48.18 v35.08,45.52
  Bottom 0.254: v39.9,37.52 39.9,37.57 37.97,39.5 37.97,42.62 v35.08,45.52 | U1.AREF 26.16,48.51 37.41,48.51 v37.74,48.18
DTR  (via drill 0.51)
  Top 0.254: SJ1.1 34.29,15.67 v36.14,17.53 | JP1.1 12.19,49.53 v12.7,50.04
  Bottom 0.254: v36.14,17.53 36.07,17.53 35.05,18.54 35.05,20.07 32.51,22.61 32.51,27.81 29.84,30.48 14.99,30.48 13.21,32.26 13.21,49.53 v12.7,50.04
GND  (via drill 0.51)
  Top 0.254: U2.32 43.99,19.86 44.45,20.32 | 53.72,26.16 53.73,26.17 U2.62 57.92,26.17 58.42,26.67 | 41.91,33.02 41.49,33.44 U2.99 41.49,35.83 41.12,36.2 40.31,36.2 40.11,35.99 40.08,35.99 40.01,35.92 | U2.81 50.49,33.62 50.22,33.35 | U2.11 37.96,27.67 v37.34,28.17 | U4.19 20.08,29.96 20.19,29.84 21.08,29.84 v21.21,29.59 | U4.3 25.39,28.46 25.27,28.57
  other vias: 34.44,5.11 39.88,35.92 42.88,11.07 55.07,19.33 74.24,34.32 60.91,28.47 63.63,17.14 61.06,17.17 76.2,17.14 28.45,39.34 52.27,26.57 23.75,24.13 17.65,44.83 10.03,38.1 14.22,45.85 19.68,10.79 20.95,10.79 19.68,9.53 20.95,9.53 3.84,6.58 9.83,6.6 32.05,15.62 28.83,19.18 31.32,6.86 24.71,15.29
  pour Bottom (isolate 0.305): 0,53.34 100.33,53.34 101.6,52.07 101.6,1.27 100.33,0 0,0
  pour Top (isolate 0.305): 0,53.34 100.33,53.34 101.6,52.07 101.6,1.27 100.33,0 0,0
  pour Top (no thermals): 19.86,12.52 19.86,11.61 19.63,11.38 19.63,10.82 19.76,10.69 20.9,10.69 21.46,11.25 21.46,12.52
  pour Top (no thermals): 19.23,11 17.4,11 17.3,11.1 17.3,12.14 16.74,12.7 16.74,14.48 16.89,14.63 17.91,14.63 18.16,14.38 18.16,13.23 18.8,12.6 18.8,11.68 19.23,11.25
  pour Top (no thermals): 19.2,9.98 17.58,9.98 17.12,9.53 16.1,9.53 14.63,8.05 14.63,6.53 15.16,5.99 18.03,5.99 19.15,7.11 19.41,7.11 19.41,9.68
  pour Top (no thermals): 21.21,9.3 21.21,7.16 21.26,7.06 21.46,7.06 22.07,6.45 25.4,6.45 25.37,8.94 24.99,9.32
MOSI-3  (via drill 0.51)
  Top 0.254: v19.68,40.13 U6.6 | U4.16 20.5,32.71 v19.18,34.04
  Bottom 0.254: 19.56,40.01 v19.68,40.13 19.18,39.62 v19.18,34.04
N$1
  Top 0.254: IC1.3 29.84,7.04 30.45,6.43 30.45,5.75 R2.2 R1.1
N$2
  Top 0.254: R6.1 76.85,34.39 LED1.A
N$3
  Top 0.254: R7.1 29.86,40.74 LED2.A
N$4  (via drill 0.51)
  Top 0.254: C4.1 36.94,12.05 v36.83,11.94 | SJ1.2 34.29,12.34 v34.27,12.32
  Bottom 0.254: v36.83,11.94 34.65,11.94 v34.27,12.32
N$5
  Top 0.61: IC1.1 27.3,5.12 Q1.1
N$11
  Top 0.254: U7.14 20,7.95 20.32,7.62 20.64,7.95 U7.15
  Top 1.016: 20.32,7.62 L1.1
  pour Top (no thermals): 19.89,8.48 19.89,6.63 20.78,6.63 20.78,6.65 20.75,6.68 20.75,8.48
N$13
  Top 0.254: U4.21 18.42,28.96 17.4,27.94 R8.1
N$14
  Top 0.254: U4.20 17.41,29.46 R9.1
N$15
  Top 0.254: R9.2 14.1,29.21 13.21,28.32 13.21,27.78 X1.D-
N$16
  Top 0.254: X1.D+ 13.1,26.44 13.46,26.8 14.72,26.8 R8.2
N$18
  Top 0.406: 13.84,33.02 F1.1
  Top 0.813: X1.VBUS 13.1,31.01 13.84,31.75 13.84,33.02
N$19
  Top 0.254: U4.25 19.74,25.71 19.43,25.4 19.43,24 | 19.43,24 19.43,20.56 C12.1 | Y2.1 19.44,24.01 19.43,24
N$20
  Top 0.254: U4.24 18.95,27.46 18.92,27.43 18.92,21.59 | 18.92,21.59 18.92,20.81 C13.1 | Y2.3 18.8,21.71 18.92,21.59
N$73
  Top 0.203: Y1.1 43.23,12.72
  Top 0.254: U2.33 44.49,16.35 43.23,15.09 43.23,12.72
N$74
  Top 0.254: U2.34 44.99,14.32 45.65,13.66 Y1.3
PA0
  Top 0.254: U2.78 51.99,38.02 54.61,40.64 83.82,40.64 91.44,48.26 U1.22
PA1
  Top 0.254: U2.77 52.49,37.63 54.86,40.01 85.72,40.01 92.71,46.99 95.25,46.99 U1.23
PA2
  Top 0.254: U2.76 52.99,37.24 55.12,39.37 86.36,39.37 92.71,45.72 U1.24
PA3
  Top 0.254: U2.75 54.99,36.96 56.77,38.73 87,38.73 92.71,44.45 95.25,44.45 U1.25
PA4
  Top 0.254: U2.74 56.3,32.17 56.64,32.51 56.64,36.45 58.29,38.1 87.63,38.1 92.71,43.18 U1.26
PA5
  Top 0.254: U2.73 56.69,31.67 57.28,32.26 57.28,36.2 58.67,37.59 88.39,37.59 92.71,41.91 95.25,41.91 U1.27
PA6
  Top 0.254: U2.72 57.08,31.17 59.44,33.53 68.07,33.53 71.5,36.96 89.03,36.96 92.71,40.64 U1.28
PA7
  Top 0.254: U2.71 57.59,30.67 59.94,33.02 86.74,33.02 93.09,39.37 95.25,39.37 U1.29
PB0  (via drill 0.51)
  Top 0.254: U2.19 34.59,23.67 v34.29,23.24 | U1.53 95.25,8.89 91.44,8.89 86.36,3.81 43.18,3.81 v39.37,7.62 | U6.5 20.95,40.01 v22.48,38.48
  Bottom 0.254: v39.37,7.62 39.37,13.84 37.34,15.88 37.34,19.3 34.29,22.35 v34.29,23.24 34.29,34.29 30.1,38.48 v22.48,38.48
PB1  (via drill 0.51)
  Top 0.254: U2.20 35.87,23.17 v35.56,22.73 | U1.52 91.95,10.16 86.11,4.32 43.94,4.32 v40.64,7.62 | U6.3 23.5,40.64 v23.62,40.39
  Bottom 0.254: v40.64,7.62 40.64,8.13 39.88,8.89 39.88,14.1 37.85,16.13 37.85,19.56 35.56,21.84 v35.56,22.73 35.18,23.11 35.18,35.94 30.73,40.39 v23.62,40.39 | J1.3 62.23,26.54 62.23,24.13 63.5,22.86 68.58,22.86 80.01,11.43 92.71,11.43 U1.52
PB2  (via drill 0.51)
  Top 0.254: U2.21 39.94,22.67 v40.77,23.5 | U1.51 95.25,11.43 92.33,11.43 85.85,4.95 44.58,4.95 v41.91,7.62 | U6.7 18.41,39.24 19.18,38.48 v20.7,38.48
  Bottom 0.254: v41.91,7.62 40.39,9.14 40.39,14.48 38.99,15.88 38.99,21.72 v40.77,23.5 40.64,23.62 37.34,23.62 36.2,24.77 36.2,28.45 37.08,29.34 37.08,36.58 31.75,41.91 30.1,41.91 29.21,41.91 22.86,41.91 20.7,39.75 v20.7,38.48 | J1.4 76.2,27.94 78.74,25.4 78.74,14.99 79.76,13.97 95.25,13.97 U1.51
PB3  (via drill 0.51)
  Top 0.254: U2.22 40.7,22.17 v40.77,22.1 | U1.50 92.84,12.7 85.6,5.46 45.34,5.46 v43.18,7.62 | v36.2,18.92 37.47,18.92 v40.01,16.38 | U4.15 21.61,33.63 v21.08,34.16
  Bottom 0.254: v40.77,22.1 39.5,20.83 39.5,18.29 40.89,16.89 40.89,16.51 | v43.18,7.62 43.18,7.75 40.89,10.03 40.89,16.51 | J1.1 63.63,30.35 64.9,29.08 64.9,26.92 65.15,26.67 75.06,26.67 77.98,23.75 77.98,14.73 80.01,12.7 U1.50 | v40.01,16.38 40.77,16.38 40.89,16.51 | v36.2,18.92 36.2,19.68 33.02,22.86 33.02,31.75 30.48,34.29 21.21,34.29 v21.08,34.16
PB4
  Top 0.254: 36.55,50.77 U1.10 34.29,48.51 34.06,48.28 33.15,47.37 33.15,22.86 34.34,21.67 U2.23
PB5
  Top 0.254: U2.24 34.08,21.17 32.64,22.61 32.64,49.4 U1.11
PB6
  Top 0.254: U1.12 32.13,50.16 32.13,22.35 33.81,20.67 U2.25
PB7
  Top 0.254: 28.56,43.05 R7.2 | 28.56,43.05 28.56,50.4 U1.13 | U2.26 40,18.67 38.61,20.07 33.66,20.07 31.62,22.1 31.62,42.16 30.61,43.18 28.69,43.18 28.56,43.05
PC0
  Top 0.254: U2.53 56.82,21.67 58.42,20.07 83.57,20.07 92.71,29.21 95.25,29.21 U1.37
PC1
  Top 0.254: U2.54 57.08,22.17 58.67,20.57 82.8,20.57 92.71,30.48 U1.36
PC2
  Top 0.254: U2.55 57.34,22.67 58.93,21.08 82.04,21.08 92.71,31.75 95.25,31.75 U1.35
PC3
  Top 0.254: U2.56 57.6,23.17 59.05,21.72 81.41,21.72 92.71,33.02 U1.34
PC4
  Top 0.254: U2.57 57.86,23.67 59.18,22.35 80.77,22.35 92.71,34.29 95.25,34.29 U1.33
PC5
  Top 0.254: U2.58 58.13,24.17 59.44,22.86 80.01,22.86 92.71,35.56 U1.32
PC6
  Top 0.254: U2.59 58.39,24.67 59.69,23.37 79.25,23.37 92.71,36.83 95.25,36.83 U1.31
PC7
  Top 0.254: U2.60 58.65,25.17 59.94,23.88 78.49,23.88 92.71,38.1 U1.30
PD7  (via drill 0.51)
  Top 0.254: U2.50 53.59,18.67 54.23,18.03 85.98,18.03 v89.41,21.46
  Bottom 0.254: v89.41,21.46 89.41,23.37 U1.38
PE3  (via drill 0.51)
  Top 0.254: v50.67,47.04 50.67,47.02 50.42,46.76 41.73,46.76 36.7,41.73 36.7,31.75 37.78,30.67 U2.5
  Bottom 0.254: v50.67,47.04 50.72,50.72 U1.5
PE4
  Top 0.254: U1.2 56.34,48.72 48.41,48.72 47.09,47.4 41.53,47.4 37.07,42.94 36.96,42.82 36.2,42.06 36.2,31.5 37.52,30.17 U2.6
PE5
  Top 0.254: U1.3 54.41,49.33 48.13,49.33 46.86,48.06 41.38,48.06 35.69,42.37 35.69,31.24 37.26,29.67 U2.7
PE6  (via drill 0.51)
  Top 0.254: U4.18 17.18,30.46 R10.2 17.16,31.86 v16.64,32.38 | U2.8 36.62,29.17 v36.07,29.59
  Bottom 0.254: v36.07,29.59 36.07,36.32 31.11,41.27 22.99,41.27 21.59,39.88 21.59,36.58 20.07,35.05 20.07,33.15 18.67,31.75 17.27,31.75 v16.64,32.38
PG0
  Top 0.254: U2.51 56.29,20.67 57.91,19.05 85.09,19.05 90.17,24.13 95.25,24.13 U1.41
PG1
  Top 0.254: U2.52 56.55,21.17 58.17,19.56 84.33,19.56 90.17,25.4 U1.40
PG2  (via drill 0.51)
  Top 0.254: U2.70 57.98,30.17 60.33,32.51 83.57,32.51 v84.2,31.88
  Bottom 0.254: U1.39 95.25,29.21 86.87,29.21 v84.2,31.88
PG5  (via drill 0.51)
  Top 0.254: U2.1 38.99,41.3 42.57,44.88 52.43,44.88 v53.19,45.64
  Bottom 0.254: U1.4 53.19,50.65 v53.19,45.64
PH3
  Top 0.254: 48.18,50.29 48.26,50.22 | 48.18,50.29 48.18,50.72 U1.6 | 48.18,50.29 46.56,48.67 41.17,48.67 35.18,42.67 35.18,26.67 36.18,25.67 U2.15
PH4
  Top 0.254: U1.7 44.25,49.33 41.05,49.33 34.67,42.95 34.67,26.42 35.92,25.17 U2.16
PH5
  Top 0.254: 41.68,50.77 U1.8 34.16,43.31 34.16,26.16 35.66,24.67 U2.17
PH6
  Top 0.254: 39.19,50.72 U1.9 33.66,45.34 33.66,25.91 35.39,24.17 U2.18
PJ2  (via drill 0.51)
  Top 0.254: U2.65 53.1,27.67 v52.45,28.32 | v57.78,45.72 v57.78,41.91 | v19.68,46.99 16.51,46.99 15.24,45.72 15.24,36.83 16.02,36.05 U6.9
  Bottom 0.254: v52.45,28.32 53.47,29.34 53.47,37.59 v57.78,41.91 | v19.68,46.99 20.32,46.35 49.15,46.35 51.44,44.07 56.13,44.07 v57.78,45.72
PJ3  (via drill 0.51)
  Top 0.254: U2.66 54,28.17 v52.45,29.72 | v56.13,45.72 v56.13,41.91 | U4.17 19.36,31.31 v16.76,33.91
  Bottom 0.254: v52.45,29.72 52.45,38.23 v56.13,41.91 | v56.13,45.72 55.12,44.7 51.69,44.7 49.4,46.99 21.08,46.99 20.19,47.88 18.41,47.88 16.51,45.97 16.51,34.16 v16.76,33.91
PL0
  Top 0.254: U2.35 45.49,14.71 50.55,9.65 88.52,9.65 92.84,13.97 95.25,13.97 U1.49
PL1
  Top 0.254: U2.36 45.99,14.97 50.8,10.16 87.63,10.16 92.71,15.24 U1.48
PL2
  Top 0.254: U2.37 46.49,15.23 51.05,10.67 86.87,10.67 92.71,16.51 95.25,16.51 U1.47
PL3
  Top 0.254: U2.38 46.99,15.49 51.31,11.18 86.11,11.18 92.71,17.78 U1.46
PL4
  Top 0.254: U2.39 47.49,15.76 51.56,11.68 85.34,11.68 92.71,19.05 95.25,19.05 U1.45
PL5
  Top 0.254: U2.40 47.99,16.02 51.82,12.19 84.58,12.19 92.71,20.32 U1.44
PL6
  Top 0.254: U2.41 48.49,16.28 52.07,12.7 83.82,12.7 92.71,21.59 95.25,21.59 U1.43
PL7
  Top 0.254: U2.42 48.99,16.54 52.32,13.21 83.06,13.21 92.71,22.86 U1.42
PWRIN
  Top 1.016: J2.VIN0 3.81,13.97 5.08,12.7 10.16,12.7 JP6.2 12.7,12.7 12.7,16.51 13.97,17.78 D1.A
RES-3
  Top 0.254: U4.12 23.11,31.75 22.73,31.37 20.32,31.37 17.91,33.78 17.91,34.67 18.41,35.18 U6.10
RESET  (via drill 0.51)
  Top 0.254: U1.RESET 33.02,5.08 33.91,5.97 33.91,10.67 36.59,13.35 C4.2 R3.1 39.37,13.72 42.99,17.34 U2.30 42.99,22.67 45.09,24.77 v52.2,24.77 | S1.3 74.3,26.29 73.91,26.67 64.77,26.67 63.63,25.53 J1.5 63.12,24.89 v60.58,24.89
  Bottom 0.254: v52.2,24.77 60.45,24.77 v60.58,24.89
RX0
  Top 0.254: U2.2 38.06,32.17 37.72,32.51 37.72,40.97 42.27,45.52 51.36,45.52 53.59,47.75 60.45,47.75 U1.0 61.59,52.7 21.34,52.7 16.89,48.26 8,48.26 7.11,47.37 7.11,45.47 8.13,44.45 JP1.3
RX1  (via drill 0.51)
  Top 0.254: U2.45 50.49,17.33 53.09,14.73 80.77,14.73 v81.28,15.24
  Bottom 0.254: v81.28,15.24 U1.19
RX2  (via drill 0.51)
  Top 0.254: U2.12 37.58,27.17 v37.21,26.8
  Bottom 0.254: U1.17 74.3,52.7 67.44,52.7 66.17,51.44 66.17,48.39 61.09,43.31 49.02,43.31 46.61,45.72 42.67,45.72 38.73,41.78 38.73,40.26 40.77,38.23 40.77,27.56 40.01,26.8 v37.21,26.8
RX3  (via drill 0.51)
  Top 0.254: U2.63 57.15,26.67 v59.69,29.21
  Bottom 0.254: v59.69,29.21 59.69,32.89 64.64,37.85 66.42,37.85 71.12,42.55 U1.15
SCK-3
  Top 0.254: U4.13 22.61,33.79 22.99,34.16 26.8,34.16 27.3,34.67 27.3,37.72 24.77,40.26 U6.2
SCL  (via drill 0.51)
  Top 0.254: U2.43 49.49,16.8 52.58,13.72 82.3,13.72 v83.82,15.24 | R5.1 86.85,36.21 v87,36.07
  Bottom 0.254: 86.36,36.21 U1.21 | v83.82,15.24 83.82,30.86 83.31,31.37 83.31,33.16 86.36,36.21 | 86.36,36.21 86.85,36.21 v87,36.07
SDA  (via drill 0.51)
  Top 0.254: U2.44 49.99,17.07 52.83,14.22 81.53,14.22 v82.55,15.24 | R4.1 82.82,36.21 v82.55,35.94
  Bottom 0.254: U1.20 83.82,49.53 82.55,48.26 v82.55,35.94 v82.55,15.24
SS-3
  Top 0.254: U4.14 22.11,34.17 22.61,34.67 26.54,34.67 26.8,34.92 26.8,37.47 26.04,38.23 24.38,38.23 22.23,40.39 U6.4
TX0
  Top 0.254: U2.3 37.8,31.67 37.21,32.26 37.21,41.33 41.99,46.1 51.18,46.1 53.34,48.26 58.42,48.26 U1.1 59.69,52.07 22.86,52.07 18.54,47.75 16.38,47.75 15.62,46.99 JP1.2
TX1  (via drill 0.51)
  Top 0.254: U2.46 50.99,17.59 53.34,15.24 78.74,15.24 v80.01,16.51
  Bottom 0.254: v80.01,16.51 80.01,49.53 U1.18
TX2  (via drill 0.51)
  Top 0.254: U2.13 40.13,26.67 40.87,25.93 v40.87,25.58
  Bottom 0.254: U1.16 72.39,52.07 67.82,52.07 66.93,51.18 66.93,48.39 61.34,42.8 48.77,42.8 46.35,45.21 43.05,45.21 39.37,41.53 39.37,40.64 41.4,38.61 41.4,26.11 v40.87,25.58
TX3  (via drill 0.51)
  Top 0.254: U2.64 56.38,27.17 v58.42,29.21
  Bottom 0.254: v58.42,29.21 58.42,32.64 64.26,38.48 65.15,38.48 68.58,41.91 U1.14
USBVCC  (via drill 0.51)
  Top 0.813: Q1.3 27.49,2.71 v27.91,2.29 | JP1.4 3.81,41.91 1.78,39.88 v1.78,8.38
  Bottom 0.813: v1.78,8.38 1.78,3.3 2.54,2.54 10.16,2.54 12.7,5.08 15.24,5.08 17.78,2.54 27.66,2.54 v27.91,2.29
VBCOMP
  Top 0.254: U4.22 18.68,28.46 17.91,27.69 17.91,26.92 17.65,26.67 C14.1
VIN  (via drill 0.51)
  Top 0.254: R1.2 29.21,3.5 v30.35,2.36
  Top 0.406: U7.8 19.34,13.56 C9.1
  Top 0.61: C9.1 21.84,13.59 22.32,13.11 U7.4 U7.3 C3.1
  Top 0.813: C3.1 24.38,11.86 v24.31,11.94
  Top 1.016: C11.+ 25.26,17.78 D1.C 19.93,15.23 19.3,14.61 19.3,13.6 C9.1
  Bottom 0.813: U1.VIN 45.72,2.52 44.17,0.96 31.75,0.96 v30.35,2.36 24.79,7.92 24.79,11.46 v24.31,11.94
  pour Top (no thermals): 22,11.25 22,9.75 22.66,9.75 22.66,11.28 22,11.28

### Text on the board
Bottom: 8-10-11
tPlace: GRN | DTR | TX0 | RX0 | 5V | GND | GND | BLK | Power | Reset | ISP | Electric Sheep | 6-15V
bPlace: + | -
tDocu: *330ohm on spi lines | *trimpot on USB VBUS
